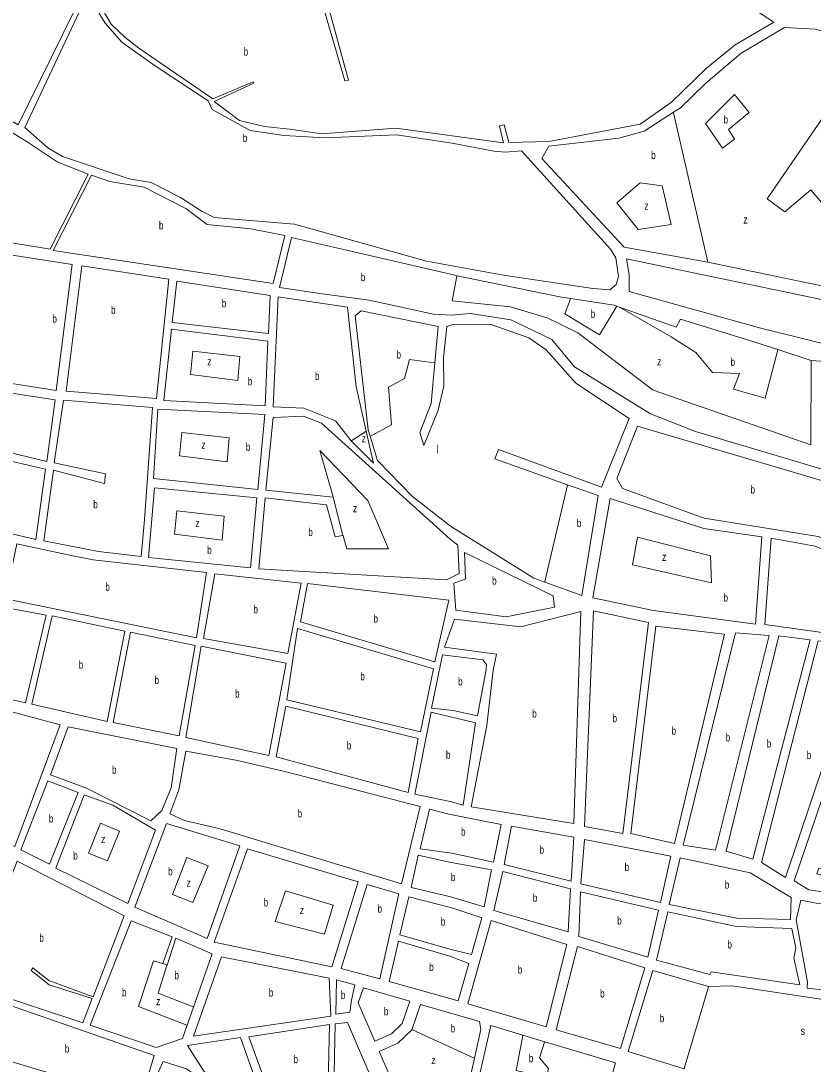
# Model space of a CAD drawing. Extents: x 639657 to 671642, y 222838 to 252123.
# Drawn here: x 647463 to 648454, y 230829 to 232133 of the extents above; entities that cross this region are included whole.
import ezdxf

# ---------------------------------------------------------------- set-up
doc = ezdxf.new("R2010")
doc.units = 0
doc.header["$LTSCALE"] = 4
doc.layers.add('1', color=7, linetype='Continuous', lineweight=13)
doc.layers.add('21', color=7, linetype='Continuous', lineweight=13)
doc.layers.add('7', color=7, linetype='Continuous')

msp = doc.modelspace()

# ---------------------------------------------------------------- linework, layer by layer
at = {"layer": '1'}
for p, q in [((648217.999, 231850.05), (648322.393, 231831.176)), ((647507.649, 231671.101), (647527.493, 231828.607)), ((647520.053, 231669.949), (647539.804, 231826.716)), ((648497.14, 231795.218), (648322.393, 231831.176)), ((648137.69, 231787.93), (648008.963, 231814.453)), ((647520.053, 231669.949), (647632.93, 231660.89)), ((647852.544, 230950.523), (647885.15, 231056.97)), ((647864.149, 230948.287), (647896.409, 231053.604)), ((647864.149, 230948.287), (647912.47, 230935.75))]:
    msp.add_line(p, q, dxfattribs=at)
for points in [[(647421.2, 232297.24), (647399.92, 232302.13), (647386.45, 232272.44), (647277.92, 232088.01), (647371.66, 232053.84), (647460.28, 232002.89), (647543.49, 232172.45), (647529.45, 232204.65), (647490.48, 232246.25), (647434.22, 232133.72), (647428.2, 232138.01), (647486.82, 232250.97), (647453.24, 232281.41), (647421.37, 232214.93), (647417.29, 232216.85), (647449.59, 232282.26)], [(648054.99, 231969.9), (648002.71, 231980.23), (647933.18, 231990.56), (647843.62, 231986.82), (647792.67, 231989.51), (647750.12, 231996.01), (647702.56, 232021.95), (647697.6, 232033.12), (647628.76, 232078.52), (647589.6, 232106.36), (647568.71, 232129.96), (647546.72, 232166.44), (647468.23, 231999.71), (647497.17, 231974.15), (647515.34, 231963.38), (647598.8, 231935.45), (647626.57, 231931.02), (647663.08, 231912.05), (647690.13, 231894.5), (647705.04, 231887.34), (647805.47, 231878.94), (647970.77, 231832.52), (648066.98, 231814.92), (648178.87, 231798.57), (648199.94, 231796.8), (648208.06, 231803.52), (648210.99, 231813.22), (648207.36, 231836.85), (648200.83, 231847.56), (648089.37, 231970.59), (648068.97, 231968.71)], [(647471.52, 231981.84), (647444.43, 231998.39), (647372.54, 232045.03), (647344.16, 232057.43), (647308.47, 232067.66), (647304.82, 232067.65), (647298.17, 232062.91), (647296.03, 232058.17), (647295.61, 232054.95), (647296.9, 232052.16), (647324.37, 232002.09), (647332.75, 231978.23), (647370.27, 231946.39), (647372.63, 231907.94), (647383.01, 231882.04), (647395.62, 231868.2), (647411.16, 231862.34), (647500.27, 231847.58), (647547.6, 231941.36), (647508.97, 231956.87)], [(647778.99, 231804.5), (647793.59, 231864.63), (647751.17, 231873), (647696.32, 231878.44), (647669.68, 231898.58), (647617.82, 231924.9), (647574.56, 231931.98), (647551.69, 231939.9), (647503.73, 231846.11)], [(647773, 231742.1), (647775.28, 231789.63), (647658.63, 231807.76), (647652.75, 231755.89)], [(647769.04, 231651.56), (647772.25, 231732.42), (647651.76, 231747.5), (647642.2, 231658.62)], [(647495.84, 231582.29), (647506.18, 231659.14), (647345.2, 231683.89), (647340.44, 231607.11), (647375.72, 231603.39), (647447.37, 231593.82)], [(647618.24, 231509.41), (647627.9, 231649.66), (647516.72, 231658.82), (647505.1, 231580.67), (647569.28, 231566.94), (647568.12, 231554.67), (647504.34, 231571.2), (647492.19, 231482.95), (647560.65, 231469.69), (647614.01, 231463.37)], [(647759.85, 231547), (647768.51, 231640.81), (647634.79, 231647.8), (647629.29, 231560.9)], [(648574.78, 231525.74), (648234.62, 231626.54), (648208.72, 231560.97), (648215.69, 231548.34), (648317.86, 231511.5), (648460.53, 231488.52), (648517.67, 231465.74), (648579.62, 231457.84)], [(647482.07, 231484.78), (647494.44, 231572.61), (647445.55, 231583.7), (647344, 231596.62), (647335.69, 231530.54), (647357.75, 231516.37), (647372.21, 231510.5)], [(647750.59, 231449.32), (647758.46, 231536.88), (647630.7, 231549.31), (647623.26, 231462.39)], [(648382.32, 231378.92), (648390.04, 231487.98), (648317.75, 231498.6), (648200.54, 231535.76), (648178.75, 231411.96), (648254.74, 231395.99)], [(648615.32, 231347.62), (648393.93, 231378.36), (648401.66, 231486.35), (648456.97, 231476.45), (648518, 231451.34), (648582.97, 231442.17), (648601.27, 231412)], [(647526.33, 231464.82), (647458.28, 231479.37), (647444.19, 231410.44), (647682.99, 231361.77), (647695.44, 231443.37), (647553.68, 231459.09)], [(648129.09, 231414.38), (648018.18, 231468.35), (648019.31, 231435.03), (648004.95, 231430.2), (648007.59, 231396.25), (648070.41, 231388.13), (648130.71, 231399.99)], [(647797.476, 231342.189), (647813.97, 231429.99), (647706.2, 231441.97), (647691.81, 231361)], [(647998.54, 231408.91), (647821.92, 231429.64), (647813.19, 231381.83), (647981.31, 231331.99)], [(647469.44, 231280.66), (647495.12, 231390.12), (647441.73, 231400.31), (647419.68, 231292.18)], [(648054.18, 231321.58), (648046.36, 231252.3), (648026.77, 231150.47), (648155.02, 231129.54), (648163.63, 231394.65), (648088.57, 231375.58), (648005.87, 231384.95), (647993.39, 231350.33), (648058.32, 231341.39)], [(648216.37, 231117.11), (648168.16, 231125.98), (648179.53, 231395.42), (648248.2, 231381.11)], [(647593.31, 231370.29), (647502.65, 231389.34), (647477.19, 231279.02), (647571.31, 231257.22)], [(647661.53, 231239.45), (647681.59, 231352.08), (647600.63, 231368.87), (647579.06, 231255.79)], [(647963.13, 231244.1), (647979.47, 231323.16), (647809.42, 231373.4), (647795.97, 231284.49)], [(648280.73, 231104.93), (648226.26, 231117.19), (648257.48, 231376.45), (648343.53, 231366.37)], [(648332.16, 231096.52), (648291.71, 231102.65), (648357.05, 231367.98), (648399.2, 231364.65)], [(648378.67, 231085.27), (648345.71, 231095.33), (648411.46, 231364.1), (648450.39, 231359.45)], [(648419.9, 231062.38), (648389.88, 231080.84), (648460.72, 231358.03), (648516.45, 231349.65)], [(647795.225, 231330.201), (647689.12, 231351.3), (647669.93, 231237.18), (647773.51, 231214.61)], [(648483.96, 231060.51), (648475.72, 231043.25), (648448.82, 231046.91), (648430.47, 231057.95), (648527.47, 231342.21), (648531.76, 231342.89), (648561.18, 231318.82), (648574.33, 231313.77), (648496.98, 231098.65), (648502.19, 231091.82), (648493.16, 231065.74), (648461.5, 231073.88), (648458.77, 231066.76)], [(647947.61, 231168.27), (647960.42, 231236.12), (647794.77, 231276.31), (647782.56, 231212.98)], [(647512.7, 231253.17), (647441.17, 231272.42), (647422.92, 231190.98), (647401.45, 231128.64), (647455.89, 231100.83)], [(648031.94, 231255.41), (647976.4, 231268.74), (647956, 231166.42), (648000.33, 231157.23), (648016.65, 231152.54)], [(647658.48, 231223.3), (647522.61, 231250.69), (647500.48, 231190.49), (647545.35, 231173.76), (647625.93, 231132.9), (647639.75, 231145.94), (647651.48, 231174.43)], [(647732.32, 231209.02), (647669.68, 231220.19), (647661.18, 231171.74), (647649.89, 231141.96), (647668.25, 231133.34), (647712.83, 231123.05), (647939.58, 231054.26), (647962.62, 231150.8), (647793.71, 231194.83)], [(647499.31, 231078.93), (647535.09, 231168.5), (647497.34, 231182.94), (647463.45, 231096.82)], [(647578.45, 231152.83), (647542.65, 231165.35), (647507.31, 231074.06), (647597.37, 231029.86), (647631.63, 231121.35)], [(648064.13, 231128.4), (647998.84, 231141.45), (647974.47, 231147.48), (647962.75, 231098.14), (648002.41, 231092.62), (648054.62, 231081.47)], [(647696.24, 230985.96), (647737.33, 231101.81), (647645.51, 231129.88), (647605.8, 231025.22)], [(648067.75, 231078.35), (648151.52, 231057.5), (648155.16, 231112.77), (648077.04, 231126.57)], [(648163.58, 231054.37), (648263.49, 231031.07), (648276.13, 231088.77), (648168.29, 231109.65)], [(647553.93, 230912.91), (647592.81, 231014.12), (647458.88, 231082.81), (647425.4, 230998.85), (647354.89, 230962.01), (647366.74, 230938.27), (647540.95, 230880.75), (647552.66, 230910.96), (647498.77, 230928.03), (647476.23, 230945.85), (647478.35, 230949.31), (647498.49, 230933.61)], [(648051.9, 231071.99), (647999.44, 231081.3), (647960.25, 231089.94), (647951.66, 231049.87), (647999.44, 231038.42), (648043.04, 231025.5)], [(648358.85, 231011.4), (648274.26, 231028.36), (648288.18, 231086.93), (648375.59, 231068.05), (648426.98, 231037.29), (648425.92, 231009.56)], [(648147.95, 230994.29), (648055.11, 231021.08), (648066.32, 231069.53), (648150.74, 231048.26)], [(648247.49, 230962.61), (648161.32, 230988.38), (648163.24, 231044.27), (648260.77, 231021.6)], [(647999.95, 230972.77), (648026.97, 230966.06), (648039.93, 231011.72), (648002.41, 231024.13), (647948.56, 231038.23), (647937.46, 230990.61)], [(648446.81, 230923.76), (648469.61, 230921.57), (648477.13, 231028.01), (648460.35, 231029.81), (648439.04, 231033.73), (648433.23, 231009.18), (648447.39, 230931.28)], [(648326.94, 230944.31), (648437.53, 230927.98), (648429.96, 230961.23), (648432.65, 230973.72), (648427.73, 230998.39), (648358.5, 231001.08), (648272.4, 231019.11), (648258.27, 230959.04), (648325.25, 230940.86)], [(648051.56, 231008.37), (648146.14, 230978.59), (648120.54, 230875.66), (648022.31, 230904.34)], [(648000.05, 230963.96), (648023.84, 230954.86), (648010.25, 230907.9), (647924.11, 230932.43), (647935.82, 230982.85)], [(648159.7, 230975.9), (648243.73, 230949.26), (648213.17, 230848.66), (648133.04, 230871.68)], [(647851.31, 230888.9), (647849.09, 230936.38), (647714.53, 230962.93), (647679.49, 230863.91)], [(647858.165, 230934.475), (647857.339, 230891.509), (647874.747, 230893.884), (647877.121, 230908.926), (647881.078, 230927.926)], [(647624.52, 230820.35), (647630.11, 230839.75), (647458.68, 230899.46), (647427.42, 230909.67), (647382.17, 230922.31), (647376.62, 230919.03), (647418.25, 230841.86), (647533.34, 230807.8), (647556.67, 230796), (647596.96, 230764.61)], [(647847.23, 230786.32), (647849.49, 230878.35), (647748.67, 230862.9), (647778.1, 230781.95), (647798.44, 230788.61)], [(647913.65, 230783.79), (647871.8, 230880.94), (647856.57, 230879.28), (647854.22, 230755.87)], [(647768.94, 230774.98), (647737.94, 230862.36), (647671.66, 230852.43), (647736.75, 230750.79)], [(647688.17, 230692.25), (647731.72, 230739.13), (647683.68, 230812.58), (647679.98, 230816.62), (647670.46, 230822.97), (647641.58, 230832.13), (647607.14, 230756.97), (647635.35, 230730.4), (647655.21, 230701.15), (647662.8, 230673.93)]]:
    msp.add_lwpolyline(points, close=True, dxfattribs=at)
for points in [[(648323.64, 232184.54), (648405.05, 232131.52), (648356.68, 232103.18), (648320.99, 232073.96), (648277.12, 232031.2), (648238.09, 232004.01), (648123.67, 231982.03), (648073.86, 231980.84), (648067.71, 232002.84), (648062.11, 232001.58), (648067.03, 231980.62), (647932.23, 231998.71), (647839.91, 231991.72), (647799.45, 231997.49), (647768.1, 232000.77), (647736.96, 232008.28), (647705.33, 232032.27), (647754.91, 232055.18), (647754.05, 232056.89), (647703.61, 232035.49), (647611.1, 232098.89), (647593.45, 232112.39), (647576.23, 232128.9), (647544.11, 232184.27)], [(647836.95, 232167.13), (647868.76, 232057.82), (647873.27, 232058.69), (647842.52, 232171.87)], [(648458.03, 231999.59), (648521.08, 232095.01), (648517.65, 232104.91), (648457.06, 232122.63), (648418.37, 232124.83), (648364.2, 232092.41), (648319.9, 232055.25), (648288.29, 232024.3), (648279.561, 232018.658)], [(648279.561, 232018.658), (648242.82, 231994.91), (648211.32, 231986.14), (648123.71, 231976.44), (648115.02, 231961.1), (648217.999, 231850.05)], [(648220.711, 231835.424), (648224.29, 231816.12), (648224.03, 231794.61), (648391.61, 231748.16), (648403.67, 231745.02), (648481.41, 231726.05), (648670.02, 231709.87), (648648.75, 231762.61), (648622.25, 231824.12), (648599.63, 231858.57), (648520.75, 231804.41), (648515.1, 231812.76), (648594.4, 231866.7), (648568.15, 231898.11), (648499.31, 231959.95)], [(648008.963, 231814.453), (648004.32, 231815.41), (647802, 231862.35), (647786.77, 231799.85), (647837.14, 231792), (647898.89, 231783.83), (647979.44, 231766.19), (648001.4, 231765.17), (648025.88, 231767.08), (648076.24, 231759.08), (648127.59, 231734.52), (648156.01, 231700.33), (648250.84, 231641.71), (648307.1, 231619.78), (648572.08, 231540.98), (648573.04, 231582.27), (648601.81, 231585.28), (648619.83, 231696.37), (648451.67, 231708.62), (648410.134, 231722.119)], [(647527.493, 231828.607), (647385.29, 231850.46), (647371.86, 231840.22), (647356.69, 231694.55), (647507.649, 231671.101)], [(647632.93, 231660.89), (647648.51, 231810.01), (647539.804, 231826.716)], [(648497.14, 231795.218), (648523.17, 231790.258), (648520.691, 231772.899), (648220.711, 231835.424)], [(647882.87, 231675.54), (647871.91, 231775.17), (647785.19, 231787.8), (647779.15, 231650.38), (647817.2, 231648.84), (647856.91, 231632.92), (647876.72, 231608.2)], [(648208.699, 231776.338), (648205.47, 231777.48), (648150.903, 231785.893), (648137.69, 231787.93)], [(648410.134, 231722.119), (648372.16, 231734.46), (648288.35, 231760.27), (648282.85, 231750.12), (648212.294, 231775.067), (648208.699, 231776.338)], [(647981.213, 231705.503), (647985.19, 231750.99), (647889.15, 231770.4), (647881.48, 231764.3), (647897.85, 231621.74), (647900.269, 231613.73)], [(648050.27, 231753.93), (648003.6, 231753.34), (647996.15, 231751.11), (647992.05, 231712.37), (647992.44, 231676.26), (647985.24, 231646.52), (647967.24, 231602.05), (647962.34, 231618.34), (647976.78, 231654.81), (647981.213, 231705.503)], [(648147.221, 231553.172), (648056.14, 231585.39), (648060.78, 231597.04), (648189.67, 231550.08), (648224.02, 231635.92), (648157.68, 231679.92), (648120.6, 231721.78), (648098.55, 231736.67), (648050.27, 231753.93)], [(647876.72, 231608.2), (647904.31, 231580.11), (647895.308, 231620.18), (647882.87, 231675.54)], [(648009.73, 231477.75), (648000.43, 231484.99), (647839.32, 231630.16), (647816.88, 231638.74), (647778.86, 231637.27), (647769.96, 231546.25), (647854.06, 231537.67), (647866.18, 231489.64)], [(647900.269, 231613.73), (647909.43, 231583.39), (647953.1, 231538.27), (648000.92, 231501.43), (648104.84, 231436.55), (648118.539, 231431.562)], [(648118.539, 231431.562), (648164.98, 231414.65), (648185.25, 231539.72), (648147.221, 231553.172)], [(647866.18, 231489.64), (647856.53, 231488.04), (647845.57, 231527.91), (647768.77, 231536.78), (647760.92, 231448.13), (647995.56, 231434.44), (648011.52, 231442.29), (648009.73, 231477.75)], [(648041.19, 231334.37), (647990.92, 231340.54), (647977.2, 231273.91), (648003.9, 231270.97), (648034.66, 231264.24), (648045.37, 231322.37)], [(648045.37, 231322.37), (648045.75, 231328.39), (648041.19, 231334.37)], [(647885.15, 231056.97), (647747.04, 231098.26), (647705.1, 230981.32), (647852.544, 230950.523)], [(647912.47, 230935.75), (647936.06, 231041.75), (647896.409, 231053.604)], [(647652.6, 230988.08), (647601.477, 231008.105), (647550.22, 230877.62), (647632.8, 230849.67), (647665.55, 230861.18), (647671.363, 230877.636), (647679.355, 230900.263)], [(647679.355, 230900.263), (647702.89, 230966.89), (647657.13, 230986.41), (647646.32, 230952.77), (647640.93, 230954.65), (647652.6, 230988.08)], [(648323.44, 230926.02), (648353.09, 230926.68), (648475.3, 230908.29), (648480.964, 230958.965)], [(648292.841, 230823.022), (648222.87, 230844.87), (648253.65, 230945.89), (648323.44, 230926.02)], [(647906.017, 230857.531), (647885.08, 230905.59), (647891.82, 230924.47), (647949.743, 230907.585)], [(647906.017, 230857.531), (647926.978, 230866.968), (647940.43, 230879.634), (647949.743, 230907.585)], [(647911.583, 230844.756), (647934.829, 230855.221), (647952.539, 230871.897), (647963.13, 230903.682), (648036.96, 230882.16)], [(648091.185, 230865.178), (648051.33, 230877.06), (648030.15, 230785.57)], [(648036.96, 230882.16), (648038.69, 230872.24), (648030.756, 230836.25)], [(648199.345, 230802.334), (648207.3, 230830.56), (648118.579, 230857.011), (648091.185, 230865.178)], [(648030.756, 230836.25), (648020.04, 230787.64), (647957.7, 230802.73), (647934.4, 230792.38), (647911.583, 230844.756)]]:
    msp.add_lwpolyline(points, dxfattribs=at)
at = {"layer": '21'}
for points in [[(648319.628, 232004.482), (648340.984, 231973.769), (648355.856, 231984.929), (648348.42, 231997.328), (648374.446, 232018.407), (648355.856, 232040.726)], [(648208.903, 231905.529), (648238.117, 231930.371), (648265.383, 231926.652), (648276.537, 231878.294), (648235.638, 231872.094)], [(647678.364, 231720.251), (647675.447, 231691.063), (647734.936, 231683.623), (647737.415, 231713.382)], [(647664.731, 231618.575), (647661.814, 231589.387), (647721.303, 231581.947), (647723.782, 231611.706)], [(647658.534, 231520.62), (647655.617, 231491.432), (647715.106, 231483.992), (647717.585, 231513.751)], [(648234.631, 231487.727), (648228.202, 231452.994), (648327.351, 231430.675), (648326.111, 231464.153)], [(647563.115, 231130.29), (647586.716, 231120.301), (647571.681, 231083.093), (647547.942, 231092.593)], [(647670.962, 231087.378), (647653.184, 231041.134), (647678.506, 231030.842), (647697.497, 231076.759)], [(647794.252, 231045.742), (647781.374, 231007.092), (647843.095, 230991.259), (647854.173, 231027.676)]]:
    msp.add_lwpolyline(points, close=True, dxfattribs=at)
for points in [[(648322.393, 231831.176), (648279.675, 232018.158), (648279.561, 232018.658)], [(648497.142, 231795.218), (648469.877, 231836.136), (648504.579, 231858.455), (648451.287, 231921.692), (648419.063, 231894.413), (648396.755, 231910.532), (648457.686, 231999.09), (648458.03, 231999.59)], [(648451.67, 231708.62), (648451.668, 231708.12), (648451.287, 231603.027), (648254.228, 231671.224), (648202.175, 231710.902), (648160.037, 231743.14), (648121.617, 231761.739), (648075.76, 231775.379), (648002.638, 231782.818), (648008.84, 231813.838), (648008.963, 231814.453)], [(648208.699, 231776.338), (648187.303, 231740.66), (648143.925, 231766.699), (648149.085, 231780.893), (648150.903, 231785.893)], [(648410.134, 231722.119), (648410.004, 231721.619), (648394.276, 231661.304), (648354.617, 231672.463), (648362.053, 231692.303), (648328.59, 231693.542), (648307.521, 231718.341), (648276.537, 231738.18), (648212.294, 231775.067)], [(647981.213, 231705.503), (647980.713, 231705.568), (647949.346, 231709.662), (647943.149, 231686.103), (647923.319, 231674.943), (647927.037, 231627.826), (647900.769, 231613.993), (647900.269, 231613.73)], [(647876.72, 231608.2), (647877.22, 231608.522), (647894.808, 231619.858), (647895.308, 231620.18)], [(647837.362, 231595.769), (647897.292, 231533.59), (647923.319, 231472.833), (647871.266, 231472.833), (647866.331, 231489.14), (647866.18, 231489.64)], [(647854.06, 231537.67), (647853.916, 231538.17), (647837.362, 231595.769)], [(648147.221, 231553.172), (648147.103, 231552.672), (648118.657, 231432.062), (648118.539, 231431.562)], [(647671.363, 230877.636), (647670.863, 230877.828), (647610.454, 230901.009), (647629.445, 230958.009), (647640.43, 230954.796), (647640.93, 230954.65)], [(647646.32, 230952.77), (647646.159, 230952.27), (647634.984, 230917.634), (647678.855, 230900.459), (647679.355, 230900.263)], [(648323.44, 230926.02), (648323.291, 230925.52), (648292.99, 230823.522), (648292.841, 230823.022)], [(647952.539, 230871.897), (647953.039, 230871.669), (648030.256, 230836.478), (648030.756, 230836.25)], [(648091.185, 230865.178), (648091.091, 230864.678), (648082.863, 230821.051), (648101.854, 230816.301), (648097.107, 230790.968), (648114.515, 230786.218)], [(648114.515, 230786.218), (648114.632, 230786.718), (648123.219, 230823.426), (648112.141, 230836.885), (648118.419, 230856.511), (648118.579, 230857.011)]]:
    msp.add_lwpolyline(points, dxfattribs=at)

# ---------------------------------------------------------------- texts
at = {"layer": '7'}
for s, width, p in [('b', 0.75, (647742.114, 232089.565)), ('b', 0.75, (648342.223, 232004.768)), ('b', 0.75, (647741.033, 231981.62)), ('b', 0.75, (648251.75, 231960.13)), ('z', 0.8, (648243.074, 231896.893)), ('b', 0.75, (647636.148, 231872.2)), ('z', 0.8, (648367.01, 231879.534)), ('b', 0.75, (647888.617, 231807.617)), ('b', 0.75, (647714.742, 231774.93)), ('b', 0.75, (647576.277, 231766.633)), ('b', 0.75, (648176.149, 231761.739)), ('b', 0.75, (647502.944, 231755.675)), ('b', 0.75, (647933.234, 231710.902)), ('z', 0.8, (647696.516, 231702.222)), ('z', 0.8, (648259.186, 231702.222)), ('b', 0.75, (648351.022, 231701.665)), ('b', 0.75, (647831.285, 231683.955)), ('b', 0.75, (647747.33, 231677.423)), ('z', 0.8, (647689.08, 231598.067)), ('b', 0.75, (647744.851, 231595.587)), ('z', 0.8, (647889.688, 231606.05)), ('b', 0.75, (648376.007, 231542.19)), ('b', 0.75, (647553.989, 231523.671)), ('z', 0.8, (647878.702, 231518.711)), ('b', 0.75, (648158.798, 231500.112)), ('z', 0.8, (647681.644, 231500.112)), ('b', 0.75, (647822.931, 231488.952)), ('b', 0.75, (647696.516, 231466.633)), ('z', 0.8, (648265.383, 231457.954)), ('b', 0.75, (648052.855, 231428.24)), ('b', 0.75, (647569.111, 231420.57)), ('b', 0.75, (648342.223, 231407.116)), ('b', 0.75, (647754.302, 231392.415)), ('b', 0.75, (647904.43, 231380.815)), ('b', 0.75, (647535.784, 231323.28)), ('b', 0.75, (647630.671, 231304.16)), ('b', 0.75, (647888.066, 231308.75)), ('b', 0.75, (648010.35, 231302.249)), ('b', 0.75, (647731.354, 231287.124)), ('b', 0.75, (648102.956, 231262.095)), ('b', 0.75, (648203.403, 231256.265)), ('b', 0.75, (648277.236, 231240.69)), ('b', 0.75, (648344.861, 231232.25)), ('b', 0.75, (647871.082, 231222.29)), ('b', 0.75, (648396.246, 231224.685)), ('b', 0.75, (647995.051, 231210.64)), ('b', 0.75, (648446.262, 231210.205)), ('b', 0.75, (647577.464, 231191.795)), ('b', 0.75, (647809.678, 231137.225)), ('b', 0.75, (647498.48, 231130.935)), ('b', 0.75, (648013.969, 231114.475)), ('z', 0.8, (647563.768, 231105.259)), ('b', 0.75, (647528.951, 231084.676)), ('b', 0.75, (648112.09, 231092.035)), ('b', 0.75, (648218.52, 231070.36)), ('b', 0.75, (647647.645, 231064.884)), ('b', 0.75, (648001.262, 231057.72)), ('z', 0.8, (647670.593, 231050.634)), ('b', 0.75, (648343.832, 231048.245)), ('b', 0.75, (648103.755, 231031.91)), ('b', 0.75, (647767.131, 231026.092)), ('b', 0.75, (647909.564, 231018.3)), ('z', 0.8, (647812.235, 231016.592)), ('b', 0.75, (647988.681, 231002.145)), ('b', 0.75, (648209.26, 231003.44)), ('b', 0.75, (647486.558, 230981.78)), ('b', 0.75, (648347.147, 230973.545)), ('b', 0.75, (647974.106, 230945.375)), ('b', 0.75, (648084.973, 230942.015)), ('b', 0.75, (647655.558, 230935.051)), ('b', 0.75, (647589.881, 230913.676)), ('b', 0.75, (647773.587, 230913.42)), ('z', 0.8, (647632.611, 230902.592)), ('b', 0.75, (647863.669, 230910.509)), ('b', 0.75, (648187.961, 230912.28)), ('b', 0.75, (647917.482, 230889.926)), ('b', 0.75, (648262.485, 230881.218)), ('b', 0.75, (648000.96, 230868.721)), ('s', 0.8, (648438.716, 230865.505)), ('b', 0.75, (647518.423, 230843.46)), ('b', 0.75, (647804.441, 230830.15)), ('z', 0.8, (647976.825, 230828.968)), ('b', 0.75, (648098.689, 230831.343))]:
    msp.add_text(s, height=10, dxfattribs=dict(at, width=width)).set_placement(p)
msp.add_text('l', height=10, dxfattribs=at).set_placement((647982.827, 231592.525))

doc.saveas('drawing.dxf')
